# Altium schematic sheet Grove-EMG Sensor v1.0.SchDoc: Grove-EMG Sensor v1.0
size 286 x 197 mm; Date: 2/16/2014 5:51:37 AM; SheetNumber: 1; Origin: Eagle; GateName_1: G$1; SymbolName_1: SEEEDSTUDIO_SCH_FRAME; LibraryName: moudle; DeviceSetName: SEEEDSTUDIO_SCH_FRAME; Sheet: Sheet:; SeeedStudio: SeeedStudio; Design: Design:; Check: Check:; Vision: Vision:
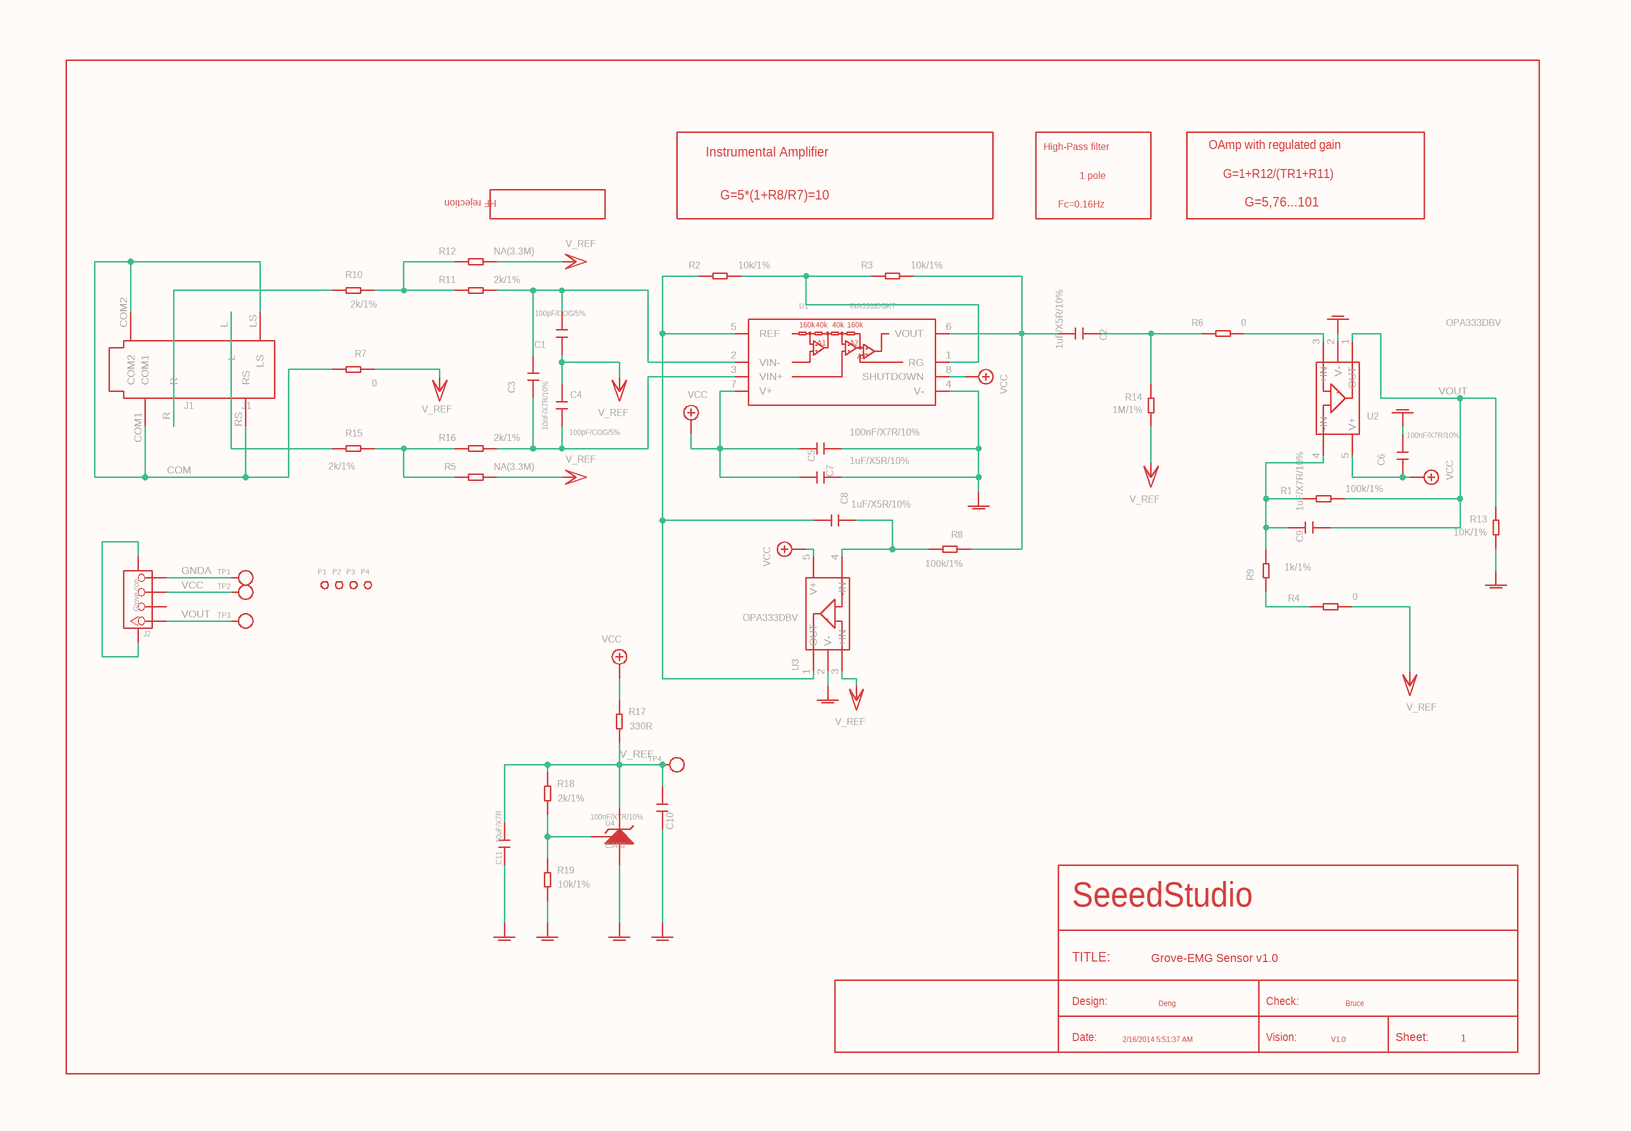
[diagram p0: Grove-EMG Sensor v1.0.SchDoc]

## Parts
C1  100pF/COG/5%  [C0603]
C2  1uF/X5R/10%  [C0603]
C3  10nF/X7R/10%  [C0603]
C4  100pF/COG/5%  [C0603]
C5  100nF/X7R/10%  [C0603]
C6  100nF/X7R/10%  [C0603]
C7  1uF/X5R/10%  [C0603]
C8  1uF/X5R/10%  [C0603]
C9  1uF/X7R/10%  [C0603]
C10  100nF/X7R/10%  [C0603]
C11  10uF/X7R  [C0805]
GND1  GNDA  (value not drawn)
GND2  GNDA  (value not drawn)
GND3  GNDA  (value not drawn)
GND4  GNDA  (value not drawn)
GND7  GNDA  (value not drawn)
GND9  GNDA  (value not drawn)
GND10  GNDA  (value not drawn)
GND11  GNDA  (value not drawn)
GND14  GNDA  (value not drawn)
J1  J1  [6P-SMD-3.5-NEW]
J2  Grove con  [4P-SMD-2.0]
P1  PAD-MARK  [ROUND-MARK-1.0]  (value not drawn)
P2  PAD-MARK  [ROUND-MARK-1.0]  (value not drawn)
P3  PAD-MARK  [ROUND-MARK-1.0]  (value not drawn)
P4  PAD-MARK  [ROUND-MARK-1.0]  (value not drawn)
P+1  V_REF
P+3  V_REF
P+5  V_REF
P+6  V_REF
P+7  V_REF
P+9  V_REF
P+10  V_REF
R1  100k/1%  [R0603]
R2  10k/1%  [R0603]
R3  10k/1%  [R0603]
R4  0  [R0603]
R5  NA(3.3M)  [R0603]
R6  0  [R0603]
R7  0  [R0603]
R8  100k/1%  [R0603]
R9  1k/1%  [R0603]
R10  2k/1%  [R0603]
R11  2k/1%  [R0603]
R12  NA(3.3M)  [R0603]
R13  10K/1%  [R0603]
R14  1M/1%  [R0603]
R15  2k/1%  [R0603]
R16  2k/1%  [R0603]
R17  330R  [R0603]
R18  2k/1%  [R0603]
R19  10k/1%  [R0603]
TP1  TP1  [TP_4545]  (value not drawn)
TP2  TP2  [TP_4545]  (value not drawn)
TP3  TP3  [TP_4545]  (value not drawn)
TP4  TP4  [TP_4545]  (value not drawn)
U1  INA331IDGKT  [MSOP-8]
U2  OPA333DBV  [SOT23-5]
U3  OPA333DBV  [SOT23-5]
U4  CJ432  [SOT23]
V1  VCC
V2  VCC
V4  VCC
V6  VCC
V18  VCC

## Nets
COM: J1.COM1 J1.COM2 J1.LS J1.RS R7.1
GNDA: J2.4 TP1.T
V_REF: C10.1 C11.2 R17.1 R18.2 TP4.T U4.2(K)
VCC: J2.3 TP2.T
VOUT: C9.2 J2.1 R1.2 R13.1 TP3.T U2.1(OUT)
NetC1_1: C1.1 C4.2 P+3.?1(VCC/2)
NetC1_2: C1.2 C3.2 R11.1 U1.2(VIN-)
NetC2_1: C2.1 R3.1 R8.2 U1.6(VOUT)
NetC2_2: C2.2 R6.2 R14.1
NetC3_1: C3.1 C4.1 R16.1 U1.3(VIN+)
NetC5_1: C5.1 C7.1 U1.7(V+) V18.?1(+5V)
NetC5_2: C5.2 C7.2 GND7.?1(GNDA) U1.4(V-)
NetC6_1: C6.1 GND4.?1(GNDA)
NetC6_2: C6.2 U2.5(V+) V1.?1(+5V)
NetC8_1: C8.1 R8.1 U3.4(-IN)
NetC8_2: C8.2 R2.2 U1.5(REF) U3.1(OUT)
NetC9_1: C9.1 R1.1 R9.1 U2.4(-IN)
NetC10_2: C10.2 GND11.?1(GNDA)
NetC11_1: C11.1 GND14.?1(GNDA)
NetGND1_?1: GND1.?1(GNDA) U2.2(V-)
NetGND2_?1: GND2.?1(GNDA) R13.2
NetGND3_?1: GND3.?1(GNDA) U3.2(V-)
NetGND9_?1: GND9.?1(GNDA) U4.3(A)
NetGND10_?1: GND10.?1(GNDA) R19.1
NetJ1_L: J1.L R15.1
NetJ1_R: J1.R R10.1
NetJ2_SS1: J2.SS1 J2.SS2
NetP+1_?1: P+1.?1(VCC/2) R12.1
NetP+5_?1: P+5.?1(VCC/2) R14.2
NetP+6_?1: P+6.?1(VCC/2) R4.2
NetP+7_?1: P+7.?1(VCC/2) R5.1
NetP+9_?1: P+9.?1(VCC/2) U3.3(+IN)
NetP+10_?1: P+10.?1(VCC/2) R7.2
NetR2_1: R2.1 R3.2 U1.1(RG)
NetR4_1: R4.1 R9.2
NetR5_2: R5.2 R15.2 R16.2
NetR6_1: R6.1 U2.3(+IN)
NetR10_2: R10.2 R11.2 R12.2
NetR17_2: R17.2 V6.?1(+5V)
NetR18_1: R18.1 R19.2 U4.1(R)
NetU1_8: U1.8(SHUTDOWN) V4.?1(+5V)
NetU3_5: U3.5(V+) V2.?1(+5V)

Not connected (* = marked no-connect by the designer): J2 2

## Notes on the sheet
- High-Pass filter
- OAmp with regulated gain
- HF rejection
- Instrumental Amplifier
- G=5*(1+R8/R7)=10
- Fc=0.16Hz
- 1 pole
- G=1+R12/(TR1+R11)
- G=5,76...101
- SeeedStudio
- TITLE:
- Design:
- Grove-EMG Sensor v1.0
- Deng
- Check:
- Bruce
- Date:
- 2/16/2014 5:51:37 AM
- Vision:
- V1.0
- Sheet:
- 1

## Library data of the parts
C1-C10 = C*-0603: Ceramic Capacitors; GateName_1: C; DeviceName: -0603; DeviceSetName: C*
C11 = C*-0805: Ceramic Capacitors; GateName_1: C; DeviceName: -0805; DeviceSetName: C*
GND1-GND4 GND7 GND9-GND11 GND14 = GNDA: SUPPLY SYMBOL; GateName_1: 1
J1 = AUDIO-6P-SMD: GateName_1: G$1; SymbolName_1: AUDIO
J2 = TWIG-4P-2.0-SMD-FEMALE-REINFORCE'DD': GateName_1: G$1; SymbolName_1: TWIG_2.0DD; DeviceName: 'DD'
P1-P4 = PAD-MARK: PARTNO: DNP; GateName_1: G$1; SymbolName_1: MARK
P+1 P+3 P+5-P+7 P+9 P+10 = VCC/2: SUPPLY SYMBOL; GateName_1: G$1
R1-R19 = R*-0603: GateName_1: R; DeviceName: -0603; DeviceSetName: R*
TP1-TP4 = PAD-TEST-POINT'4545': PARTNO: DNP; GateName_1: TP; SymbolName_1: TEST_POINT; DeviceName: '4545'
U1 = INA331EA: GateName_1: G$1; SymbolName_1: INA331; DeviceName: EA
U2 U3 = OPA333DBV: 1.8V,Micro power CMOS oprational amplifiers Zero-Drift Series  http://www.ti.com.cn/cn/lit/ds/symlink/opa333.pdf; GateName_1: G$1; SymbolName_1: OPA333; DeviceName: DBV
U4 = REFERENCE-SOURCE: CJ432,AZ432 or other Adjustable Reference Source
V1 V2 V4 V6 V18 = +5V: SUPPLY SYMBOL; SymbolName_1: +05V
